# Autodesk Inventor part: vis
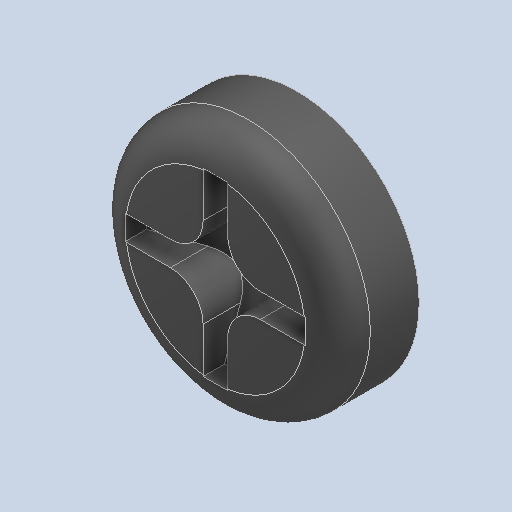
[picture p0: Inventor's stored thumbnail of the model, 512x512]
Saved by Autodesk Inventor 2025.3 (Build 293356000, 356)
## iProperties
Created: 2026-10
Part Number: vis
Material: Acier
Document SubType Name: Modeling
Designer: Luis M
Density: 7.85 g/cm^3
Appearance: Valor por defecto
Author: Luis M
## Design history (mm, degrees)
feature "Corps1"
node "Sólido1"
